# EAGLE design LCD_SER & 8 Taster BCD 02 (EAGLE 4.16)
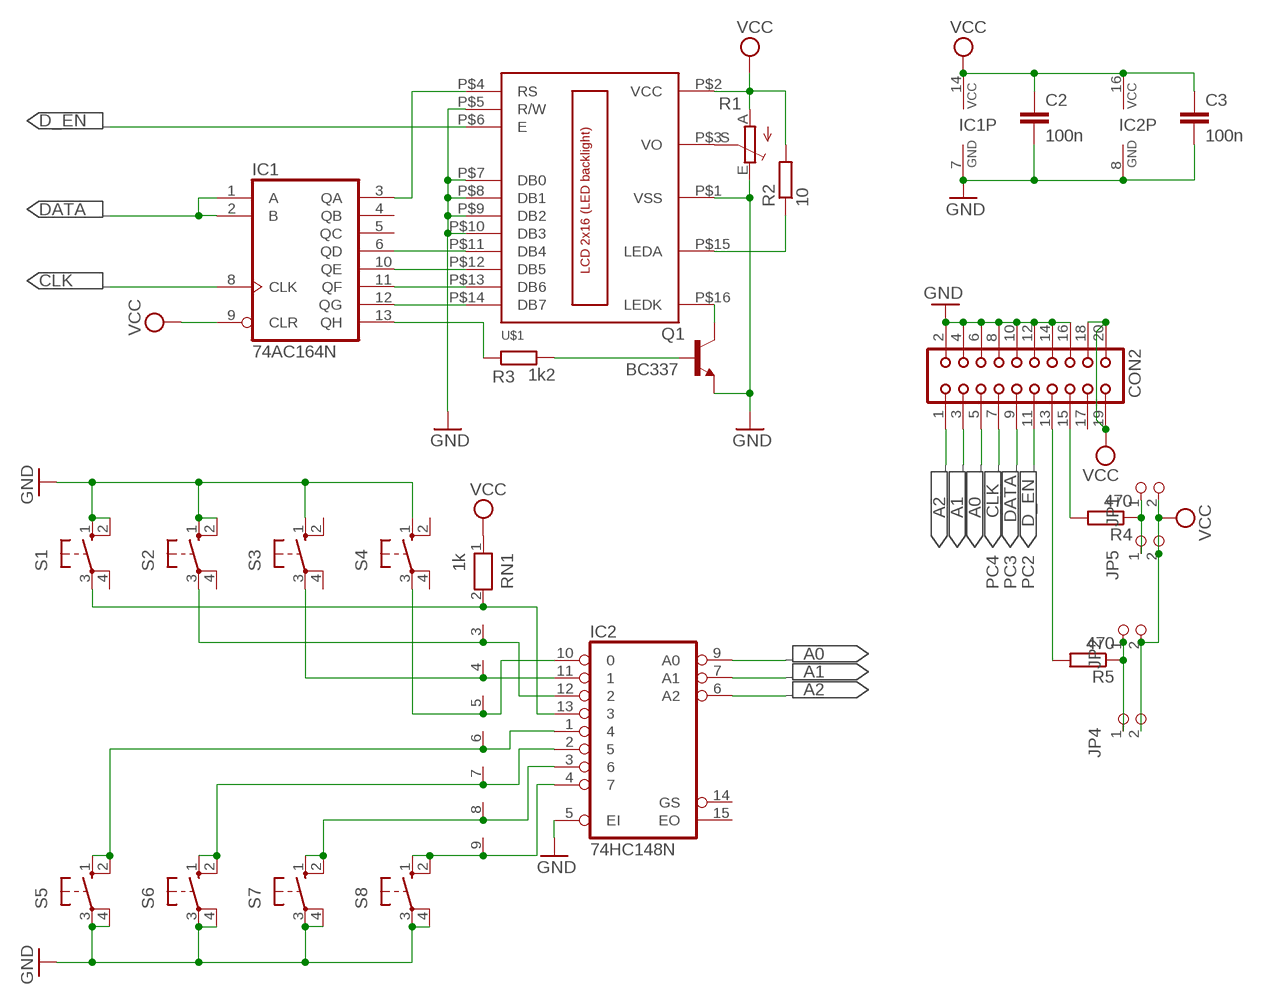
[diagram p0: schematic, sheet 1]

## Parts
C2  100n  C-EU050-025X075  [C050-025X075]
C3  100n  C-EU050-025X075  [C050-025X075]
CON2  CON20  [CON20]
IC1  74AC164N  [DIL14]
IC2  74HC148N  [DIL16]
JP1  PINHD-1X2  [1X02]
JP2  PINHD-1X2  [1X02]
JP4  PINHD-1X2  [1X02]
JP5  PINHD-1X2  [1X02]
Q1  BC337  BC337-16  [TO92]
R1  TRIM_EU-PT10  [PT-10]
R2  10  R-EU_0207/10  [0207/10]
R3  1k2  R-EU_0207/10  [0207/10]
R4  470  R-EU_0207/15  [0207/15]
R5  470  R-EU_0207/15  [0207/15]
RN1  1k  RN08  [RN-9]
S1  10-XX  [B3F-10XX]
S2  10-XX  [B3F-10XX]
S3  10-XX  [B3F-10XX]
S4  10-XX  [B3F-10XX]
S5  10-XX  [B3F-10XX]
S6  10-XX  [B3F-10XX]
S7  10-XX  [B3F-10XX]
S8  10-XX  [B3F-10XX]
U$1  LCD_2X16_PC  [PS-1602-F]

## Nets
A0: CON2.5 IC2.9(A0)
A1: CON2.3 IC2.7(A1)
A2: CON2.1 IC2.6(A2)
CLK: CON2.7 IC1.8(CLK)
D_EN: CON2.11 U$1.P$6(E)
DATA: CON2.9 IC1.1(A) IC1.2(B)
GND: C2.2 C3.2 CON2.2 CON2.4 CON2.6 CON2.8 CON2.10 CON2.12 CON2.14 CON2.16 IC1.7(GND) IC2.5(EI) IC2.8(GND) Q1.1(E) R1.E S1.1(S) S1.2(S1) S2.1(S) S2.2(S1) S3.1(S) S4.1(S) S5.3(P) S5.4(P1) S6.3(P) S6.4(P1) S7.3(P) S7.4(P1) S8.3(P) S8.4(P1) U$1.P$1(VSS) U$1.P$5(R/W) U$1.P$7(DB0) U$1.P$8(DB1) U$1.P$9(DB2) U$1.P$10(DB3)
N$1: IC1.6(QD) U$1.P$11(DB4)
N$2: IC1.10(QE) U$1.P$12(DB5)
N$3: IC1.11(QF) U$1.P$13(DB6)
N$4: IC1.12(QG) U$1.P$14(DB7)
N$5: Q1.3(C) U$1.P$16(LEDK)
N$6: IC1.3(QA) U$1.P$4(RS)
N$7: R2.1 U$1.P$15(LEDA)
N$8: IC1.13(QH) R3.1
N$9: R1.S U$1.P$3(VO)
N$10: Q1.2(B) R3.2
N$12: CON2.15 R4.2
N$14: IC2.13 RN1.2 S1.3(P)
N$15: IC2.12 RN1.3 S2.3(P)
N$16: IC2.10 RN1.5 S4.3(P)
N$17: IC2.4 RN1.9 S8.1(S) S8.2(S1)
N$18: IC2.11 RN1.4 S3.3(P)
N$19: IC2.1 RN1.6 S5.1(S) S5.2(S1)
N$20: IC2.2 RN1.7 S6.1(S) S6.2(S1)
N$21: IC2.3 RN1.8 S7.1(S) S7.2(S1)
N$26: CON2.13 R5.2
N$27: JP2.1 JP4.1 R5.1
N$28: JP1.1 JP5.1 R4.1
VCC: C2.1 C3.1 CON2.18 CON2.19 CON2.20 IC1.9(CLR) IC1.14(VCC) IC2.16(VCC) JP1.2 JP2.2 JP4.2 JP5.2 R1.A R2.2 RN1.1 U$1.P$2(VCC)
Unconnected: CON2.17 IC1.4(QB) IC1.5(QC) IC2.14(GS) IC2.15(EO) S1.4(P1) S2.4(P1) S3.2(S1) S3.4(P1) S4.2(S1) S4.4(P1)

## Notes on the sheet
- A2 | A1 | A0
- PC4 | PC3 | PC2
- A0
- A1
- A2

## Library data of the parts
C2 C3 = rcl:C-EU: CAPACITOR, European symbol
CON2 = con-harting:CON20: CONNECTOR
IC1 = 74xx-eu:74*164: 8-bit parallel out SHIFT REGISTER
IC2 = 74xx-eu:74*148: 10-line to 4-line and 8-line to 3-line PRIORITY ENCODER
JP1 JP2 JP4 JP5 = pinhead 02:PINHD-1X2: PIN HEADER
Q1 = transistor-npn:BC337*: NPN Transistor
R1 = pot:TRIM_EU-: POTENTIOMETER
R2-R5 = rcl:R-EU_: RESISTOR, European symbol
RN1 = resistor-net:RN08: RESISTOR NETWORK
S1-S8 = switch-omron:10-XX: OMRON SWITCH
U$1 = lcd_2x16_led_backlight:LCD_2X16_PC

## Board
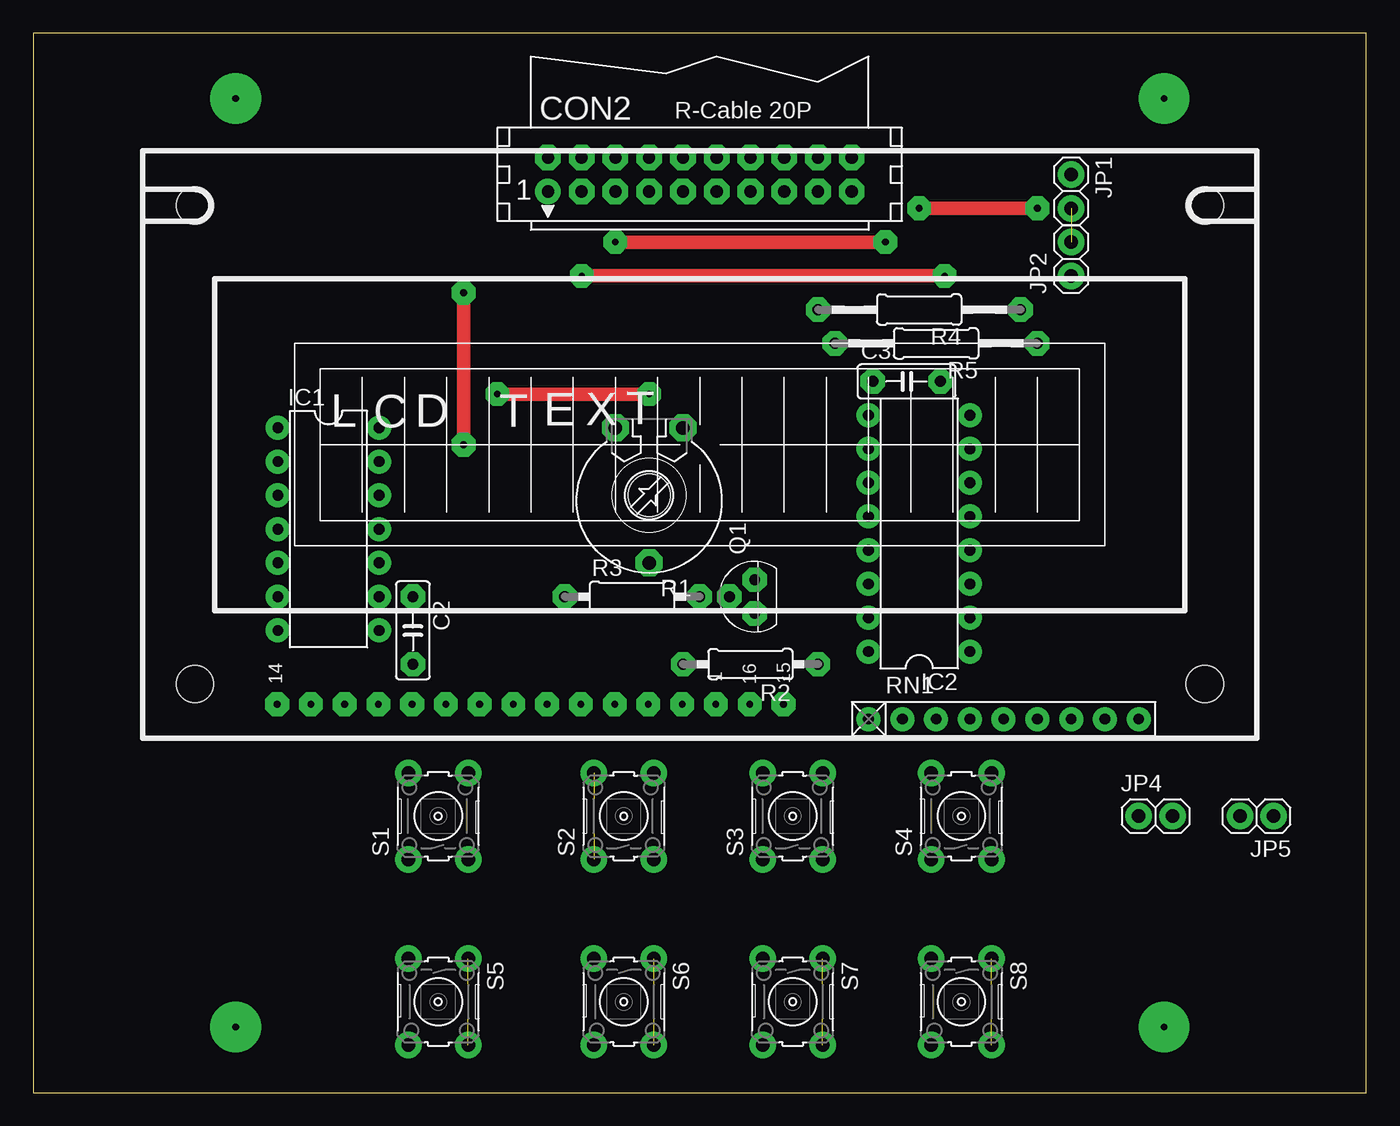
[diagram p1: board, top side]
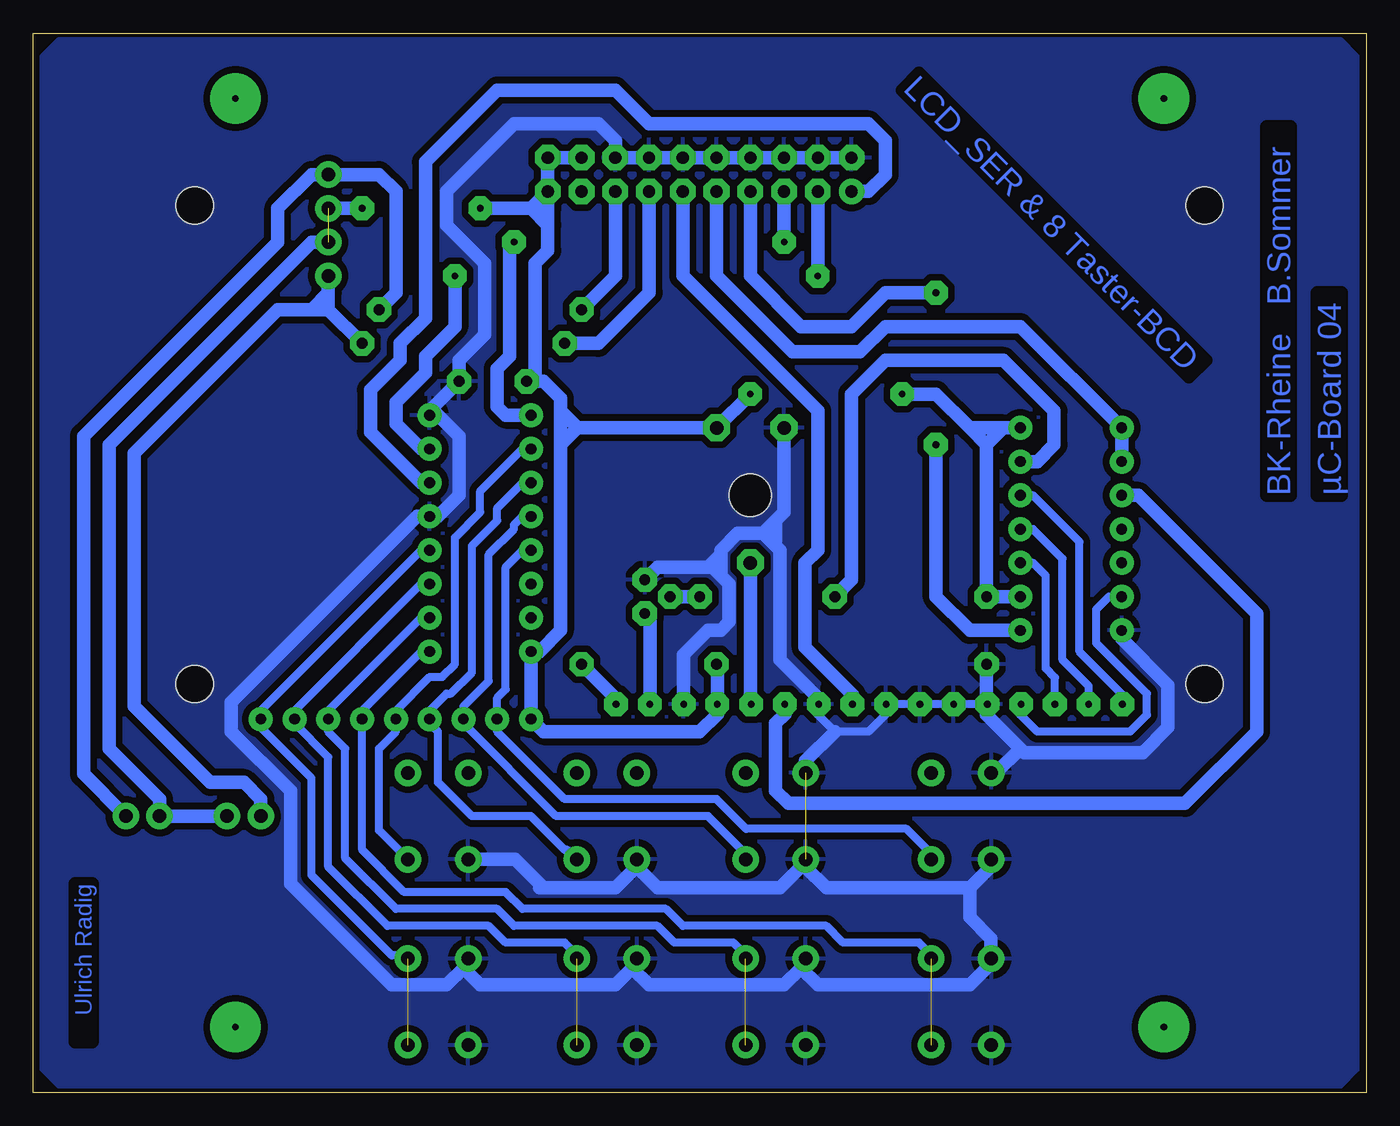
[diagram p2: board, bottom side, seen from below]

Size 100.31 x 79.68 mm. Coordinates in mm from the lower left corner, seen from the top.
Outline: 0,0 100.31,0 100.31,79.68 0,79.68 0,0
Copper layers (1*16): Top 0.035mm / dielectric 1.5mm / Bottom 0.035mm
Design rules "sommer_02_Ätzen": minimum track width 24mil, minimum drill 0.5mm, track to track 20mil, track to pad 24mil, pad to pad 20mil, via to via 20mil, smd to smd 8mil, copper to edge 0mil, drill to drill 8mil, minimum pad ring 20mil, minimum via ring 20mil, stop-mask expansion 4mil, vias tented up to drill 0mil, thermal gap 20mil
Holes 3.2 mm at 46.35,44.92

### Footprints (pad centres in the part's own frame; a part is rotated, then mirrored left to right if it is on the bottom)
C050-025X075 = drill 0.813 octagon: 1 -2.54,0; 2 2.54,0
CON20 = drill 0.914 round: 1 -11.43,-1.27 | drill 0.914 octagon: 2 -11.43,1.27; 3 -8.89,-1.27; 4 -8.89,1.27; 5 -6.35,-1.27; 6 -6.35,1.27; 7 -3.81,-1.27; 8 -3.81,1.27; 9 -1.27,-1.27; 10 -1.27,1.27; 11 1.27,-1.27; 12 1.27,1.27; 13 3.81,-1.27; 14 3.81,1.27; 15 6.35,-1.27; 16 6.35,1.27; 17 8.89,-1.27; 18 8.89,1.27; 19 11.43,-1.27; 20 11.43,1.27
DIL14 = drill 0.813 long: 1 -7.62,-3.81; 2 -5.08,-3.81; 3 -2.54,-3.81; 4 0,-3.81; 5 2.54,-3.81; 6 5.08,-3.81; 7 7.62,-3.81; 8 7.62,3.81; 9 5.08,3.81; 10 2.54,3.81; 11 0,3.81; 12 -2.54,3.81; 13 -5.08,3.81; 14 -7.62,3.81
DIL16 = drill 0.813 long: 1 -8.89,-3.81; 2 -6.35,-3.81; 3 -3.81,-3.81; 4 -1.27,-3.81; 5 1.27,-3.81; 6 3.81,-3.81; 7 6.35,-3.81; 8 8.89,-3.81; 9 8.89,3.81; 10 6.35,3.81; 11 3.81,3.81; 12 1.27,3.81; 13 -1.27,3.81; 14 -3.81,3.81; 15 -6.35,3.81; 16 -8.89,3.81
1X02 = drill 1.016 long: 1 -1.27,0; 2 1.27,0
TO92 = drill 0.813 octagon: 1 1.27,0; 2 0,1.905; 3 -1.27,0
PT-10 = drill 1.016 octagon: A -2.54,-5.08; E 2.54,-5.08; S 0,5.08
0207/10 = drill 0.813 octagon: 1 -5.08,0; 2 5.08,0
0207/15 = drill 0.813 octagon: 1 -7.62,0; 2 7.62,0
RN-9 = drill 0.813 long: 1 -10.16,0; 2 -7.62,0; 3 -5.08,0; 4 -2.54,0; 5 0,0; 6 2.54,0; 7 5.08,0; 8 7.62,0; 9 10.16,0
B3F-10XX = drill 1.016 long: 1 -3.251,2.261; 2 3.251,2.261; 3 -3.251,-2.261; 4 3.251,-2.261
PS-1602-F = drill 0.5 pad 1.778 octagon: P$1 1.21,-19.52; P$2 -1.33,-19.52; P$3 -3.87,-19.52; P$4 -6.41,-19.52; P$5 -8.95,-19.52; P$6 -11.49,-19.52; P$7 -14.03,-19.52; P$8 -16.57,-19.52; P$9 -19.11,-19.52; P$10 -21.65,-19.52; P$11 -24.19,-19.52; P$12 -26.73,-19.52; P$13 -29.27,-19.52; P$14 -31.81,-19.52; P$15 6.29,-19.52; P$16 3.75,-19.52 | hole 2.8: -38,-18; 38,-18; 38,18; -38,18

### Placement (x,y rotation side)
C2  28.57,34.76 270 top
C3  65.72,53.49 0 top
CON2  50.16,69.05 0 top
IC1  22.22,42.38 270 top
IC2  66.67,42.06 90 top
JP1  78.1,67.78 270 top
JP2  78.1,62.7 90 top
JP4  84.45,20.79 0 top
JP5  92.07,20.79 180 top
Q1  54.29,37.3 90 top
R1  46.35,44.92 180 top
R2  53.97,32.22 180 top
R3  45.07,37.3 0 top
R4  66.67,58.89 180 top
R5  67.94,56.35 180 top
RN1  73.02,28.09 0 top
S1  30.47,20.79 90 top
S2  44.45,20.79 90 top
S3  57.15,20.79 90 top
S4  69.84,20.79 90 top
S5  30.47,6.82 270 top
S6  44.45,6.82 270 top
S7  57.15,6.82 270 top
S8  69.84,6.82 270 top
U$1  50.16,48.73 0 top

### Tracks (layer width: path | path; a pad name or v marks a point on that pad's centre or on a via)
A0  (via drill 0.5 pad 1.78)
  Top 1.016: v43.81,63.97 v64.13,63.97
  Bottom 1.016: IC2.9 64.77,50.95 65.4,51.59 65.4,54.45 64.45,55.4 64.45,63.65 v64.13,63.97 | v43.81,63.97 CON2.5
A1  (via drill 0.5 pad 1.78)
  Top 1.016: v41.27,61.43 v68.57,61.43
  Bottom 1.016: v41.27,61.43 CON2.3 | v68.57,61.43 68.57,57.62 70.8,55.4 70.8,54.13 73.02,51.91 73.02,50.32 71.11,48.41 IC2.7
A2
  Bottom 1.016: CON2.1 37.46,67.78 36.19,69.05 36.19,71.59 37.46,72.86 53.97,72.86 56.51,75.4 65.4,75.4 70.8,70 70.8,58.25 72.7,56.35 72.7,55.08 74.92,52.86 74.92,49.68 71.11,45.87 IC2.6
CLK  (via drill 0.5 pad 1.78)
  Top 1.016: v32.38,48.73 v32.38,60.16
  Bottom 1.016: CON2.7 46.35,61.43 42.54,57.62 38.73,57.62 36.19,60.16 v32.38,60.16 | v32.38,48.73 32.38,37.3 29.84,34.76 IC1.8
D_EN
  Bottom 1.016: CON2.11 51.43,61.43 41.27,51.27 41.27,40.79 42.22,39.84 42.22,33.49 38.67,29.94 U$1.P$6
DATA
  Bottom 1.016: IC1.2 IC1.1 26.03,57.62 36.19,57.62 38.1,55.71 43.18,55.71 48.89,61.43 CON2.9
GND  (1 unrouted)
  Bottom 0.61: U$1.P$10 U$1.P$9 | U$1.P$9 31.1,29.21 31.11,29.2 | U$1.P$9 33.48,29.21 33.49,29.2 33.5,29.21 U$1.P$8 36.03,29.21 36.03,29.2 36.04,29.21 U$1.P$7 36.13,28.47 37.46,27.14 40,27.14 41.27,28.41 41.27,29.04 41.21,29.11 U$1.P$5
  Bottom 1.016: S4.1 64.05,17.54 62.07,15.55 | 62.07,15.55 61.91,15.39 | 54.88,17.02 S3.1 | 54.88,17.02 56.51,15.39 62.23,15.39 62.07,15.55 | 62.07,15.55 | 54.88,17.02 54.88,16.94 53.34,15.39 44.13,15.39 42.18,17.34 S2.1 42.18,16.94 40.64,15.39 29.84,15.39 | S1.1 28.21,17.02 29.84,15.39 | 29.84,15.39 29.84,13.17 28.25,11.58 28.25,10.31 28.21,10.27 S5.3 28.21,9.72 29.84,8.09 41.27,8.09 42.54,9.36 | IC1.7 18.41,34.12 14.92,30.63 14.92,27.46 16.82,25.55 25.71,25.55 26.03,25.87 | 26.03,25.87 28.57,28.41 28.57,29.04 | 28.57,29.04 28.51,29.11 U$1.P$10 | 28.57,29.04 C2.2 | 41.27,29.04 41.27,29.68 44.13,32.54 44.13,40.79 45.4,42.06 | 45.4,42.06 47.3,42.06 48.57,40.79 48.57,40.48 | U$1.P$1 51.37,32.91 49.53,34.76 48.57,34.76 47.94,35.39 47.94,38.25 48.57,38.89 | CON2.2 CON2.4 CON2.6 CON2.8 CON2.10 CON2.12 CON2.14 CON2.16 56.51,71.59 57.78,72.86 64.13,72.86 69.21,67.78 69.21,65.24 66.35,62.38 66.35,56.98 68.26,55.08 C3.2 70.48,51.27 IC2.8 69.84,50.95 68.26,49.37 68.26,44.92 69.84,43.33 IC2.5 71.43,43.33 85.4,29.36 85.4,27.14 80.96,22.7 80.96,15.71 73.34,8.09 69.21,8.09 67.94,9.36 | 48.57,40.48 48.57,38.89 | Q1.1 53.34,39.52 49.53,39.52 | 49.53,39.52 49.21,39.52 48.57,38.89 | 48.57,40.48 49.53,39.52 | R1.E 43.81,43.65 44.13,43.33 | 45.4,42.06 44.13,43.33 | 44.45,41.43 44.45,43.02 44.13,43.33 | S2.2 42.18,24.96 40,27.14 | S1.2 27.86,24.04 26.03,25.87 | 67.94,9.36 66.67,8.09 56.51,8.09 55.24,9.36 | 55.24,9.36 53.97,8.09 43.81,8.09 42.54,9.36 | S6.3 42.18,9.72 42.54,9.36 | S7.3 54.88,9.72 55.24,9.36 | S8.3 67.58,9.72 67.94,9.36
  pour Bottom: 1.9,79.21 98.42,79.21 99.69,77.94 99.69,1.74 98.42,0.47 1.9,0.47 0.63,1.74 0.63,77.94
N$1
  Bottom 0.61: IC1.6 19.36,37.3 20.31,36.35 20.31,33.81 16.5,30 16.5,28.41 17.77,27.14 24.76,27.14 26.03,28.41 26.03,29.04 25.97,29.11 U$1.P$11
N$2
  Bottom 0.61: U$1.P$12 23.43,31.21 24.12,31.9 24.12,38.89 25.08,39.84 IC1.10
N$3
  Bottom 0.61: U$1.P$13 20.89,30.57 22.86,32.54 22.86,40.16 25.08,42.38 IC1.11
N$4
  Bottom 0.61: U$1.P$14 18.35,29.94 21.58,33.17 21.58,41.43 25.08,44.92 IC1.12
N$5
  Bottom 1.016: U$1.P$16 53.91,35.65 Q1.3
N$6
  Bottom 1.016: IC1.3 17.14,44.92 8.25,36.03 8.25,27.14 13.65,21.74 43.49,21.74 44.45,22.7 44.45,27.77 43.75,28.47 U$1.P$4
N$7
  Bottom 1.016: U$1.P$15 56.45,29.62 R2.1
N$8
  Bottom 1.016: IC1.13 24.76,47.46 23.49,48.73 23.49,51.27 27.3,55.08 36.19,55.08 38.73,52.54 38.73,38.57 R3.1
N$9
  Bottom 1.016: U$1.P$3 46.29,29.62 46.35,29.68 R1.S
N$10
  Bottom 1.016: R3.2 Q1.2
N$12
  Bottom 1.016: CON2.15 56.51,61.43 R4.2
N$13  (via drill 0.5 pad 3.81)
  other vias: 15.24,4.92
N$14
  Bottom 0.61: S1.3 32.74,17.97 34.6,19.84 46.67,19.84 48.89,22.06 60.32,22.06 65.4,27.14 RN1.2 65.4,29.68 64.77,30.31 64.77,39.52 63.5,40.79 IC2.13
N$15
  Bottom 0.61: S2.3 46.71,17.97 49.53,20.79 60.96,20.79 67.94,27.77 RN1.3 67.94,29.04 66.03,30.95 66.03,40.48 64.13,42.38 64.13,42.7 63.5,43.33 IC2.12
N$16
  Bottom 0.61: IC2.10 63.5,48.41 66.67,45.24 66.67,43.65 68.57,41.74 68.57,32.22 69.53,31.27 70.48,31.27 73.02,28.73 RN1.5 73.02,27.14 74.29,25.87 74.29,19.72 S4.3
N$17  (1 unrouted)
  Bottom 0.61: S8.1 72.35,10.31 73.34,10.31 79.37,16.34 79.37,23.65 83.18,27.46 RN1.9 83.18,28.73 71.11,40.79 IC2.4
N$18
  Bottom 0.61: 59.41,17.97 S3.3 60.12,18.25 60.32,18.25 62.86,20.79 67.3,20.79 69.84,23.33 69.84,27.14 70.48,27.77 RN1.4 70.48,28.73 69.21,30 68.89,30 67.3,31.58 67.3,41.11 65.4,43.02 65.4,43.97 63.5,45.87 IC2.11
N$19  (1 unrouted)
  Bottom 0.61: S5.1 32.74,10.35 33.65,11.27 39.37,11.27 40.64,12.54 51.43,12.54 52.7,13.81 63.5,13.81 64.77,15.08 72.38,15.08 75.56,18.25 RN1.6 75.56,28.73 71.11,33.17 IC2.1
N$20  (1 unrouted)
  Bottom 0.61: S6.1 46.71,10.35 47.62,11.27 52.07,11.27 53.34,12.54 64.13,12.54 65.4,13.81 73.02,13.81 76.83,17.61 76.83,25.87 78.1,27.14 RN1.7 78.1,28.73 71.11,35.71 IC2.2
N$21  (1 unrouted)
  Bottom 0.61: S7.1 59.41,10.35 60.32,11.27 64.77,11.27 66.03,12.54 73.66,12.54 78.1,16.98 78.1,25.23 80.64,27.77 RN1.8 80.64,28.73 71.11,38.25 IC2.3
N$23  (via drill 0.5 pad 3.81)
  other vias: 85.08,4.92
N$24  (via drill 0.5 pad 3.81)
  other vias: 85.08,74.77
N$25  (via drill 0.5 pad 3.81)
  other vias: 15.24,74.77
N$26
  Bottom 1.016: CON2.13 53.97,60.16 57.78,56.35 R5.2
N$27
  Bottom 1.016: 78.1,58.89 R5.1 | 78.1,58.89 78.1,60.16 | 78.1,60.16 JP2.1 | 79.37,58.89 81.91,58.89 92.7,48.09 92.7,29.04 86.99,23.33 84.45,23.33 83.18,22.06 JP4.1 | 79.37,58.89 78.1,58.89 | 79.37,58.89 78.1,60.16
N$28
  Bottom 1.016: R4.1 73.02,60.16 73.02,67.78 74.29,69.05 JP1.1 79.37,69.05 81.91,66.51 81.91,63.97 96.52,49.37 96.52,23.96 JP5.1
N$29
  pour Bottom: 1.9,77.94 98.42,77.94 98.42,3.01 97.15,1.74 1.9,1.74
VCC  (via drill 0.5 pad 1.78)  (1 unrouted)
  Top 1.016: v34.92,52.54 v46.35,52.54 | v66.67,66.51 v75.56,66.51
  Bottom 1.016: IC1.9 C2.1 28.57,48.73 | 27.3,50 IC1.14 | 28.57,48.73 27.3,50 | R2.2 48.83,32.16 U$1.P$2 48.83,28.47 50.16,27.14 61.91,27.14 RN1.1 IC2.16 62.23,33.17 60.64,34.76 60.64,48.73 | 60.64,51.27 60.64,48.73 | 60.64,51.27 60.64,52.22 61.91,53.49 C3.1 62.54,54.13 62.54,62.38 61.59,63.34 61.59,65.24 | CON2.18 CON2.20 CON2.19 | 59.37,50 60.64,51.27 | 59.37,50 60.64,48.73 | 59.37,50 R1.A v46.35,52.54 | 61.59,65.24 61.59,66.51 | 61.59,66.51 CON2.19 | 28.57,48.73 29.84,50 | 27.3,50 29.84,50 | 29.84,50 32.38,52.54 v34.92,52.54 | 61.59,66.51 62.86,66.51 | 62.86,66.51 v66.67,66.51 | 62.86,66.51 CON2.19 | 61.59,65.24 62.86,66.51 | v75.56,66.51 JP1.2 | JP2.2 79.37,63.97 94.61,48.73 94.61,25.87 90.8,22.06 JP5.2 JP4.2

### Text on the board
Bottom: LCD_SER & 8 Taster-BCD | µC-Board 04 | BK-Rheine B.Sommer | Ulrich Radig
